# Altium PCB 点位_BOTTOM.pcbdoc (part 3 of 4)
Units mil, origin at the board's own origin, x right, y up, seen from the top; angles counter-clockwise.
Board outline 5102.8 x 4152 mil, 8 copper layers (Top Layer, GND1, 内层2, VCC, 内层4, Inner5, GND2, Bottom Layer); 209 components, 325 nets, 527 pads, 1119 vias.
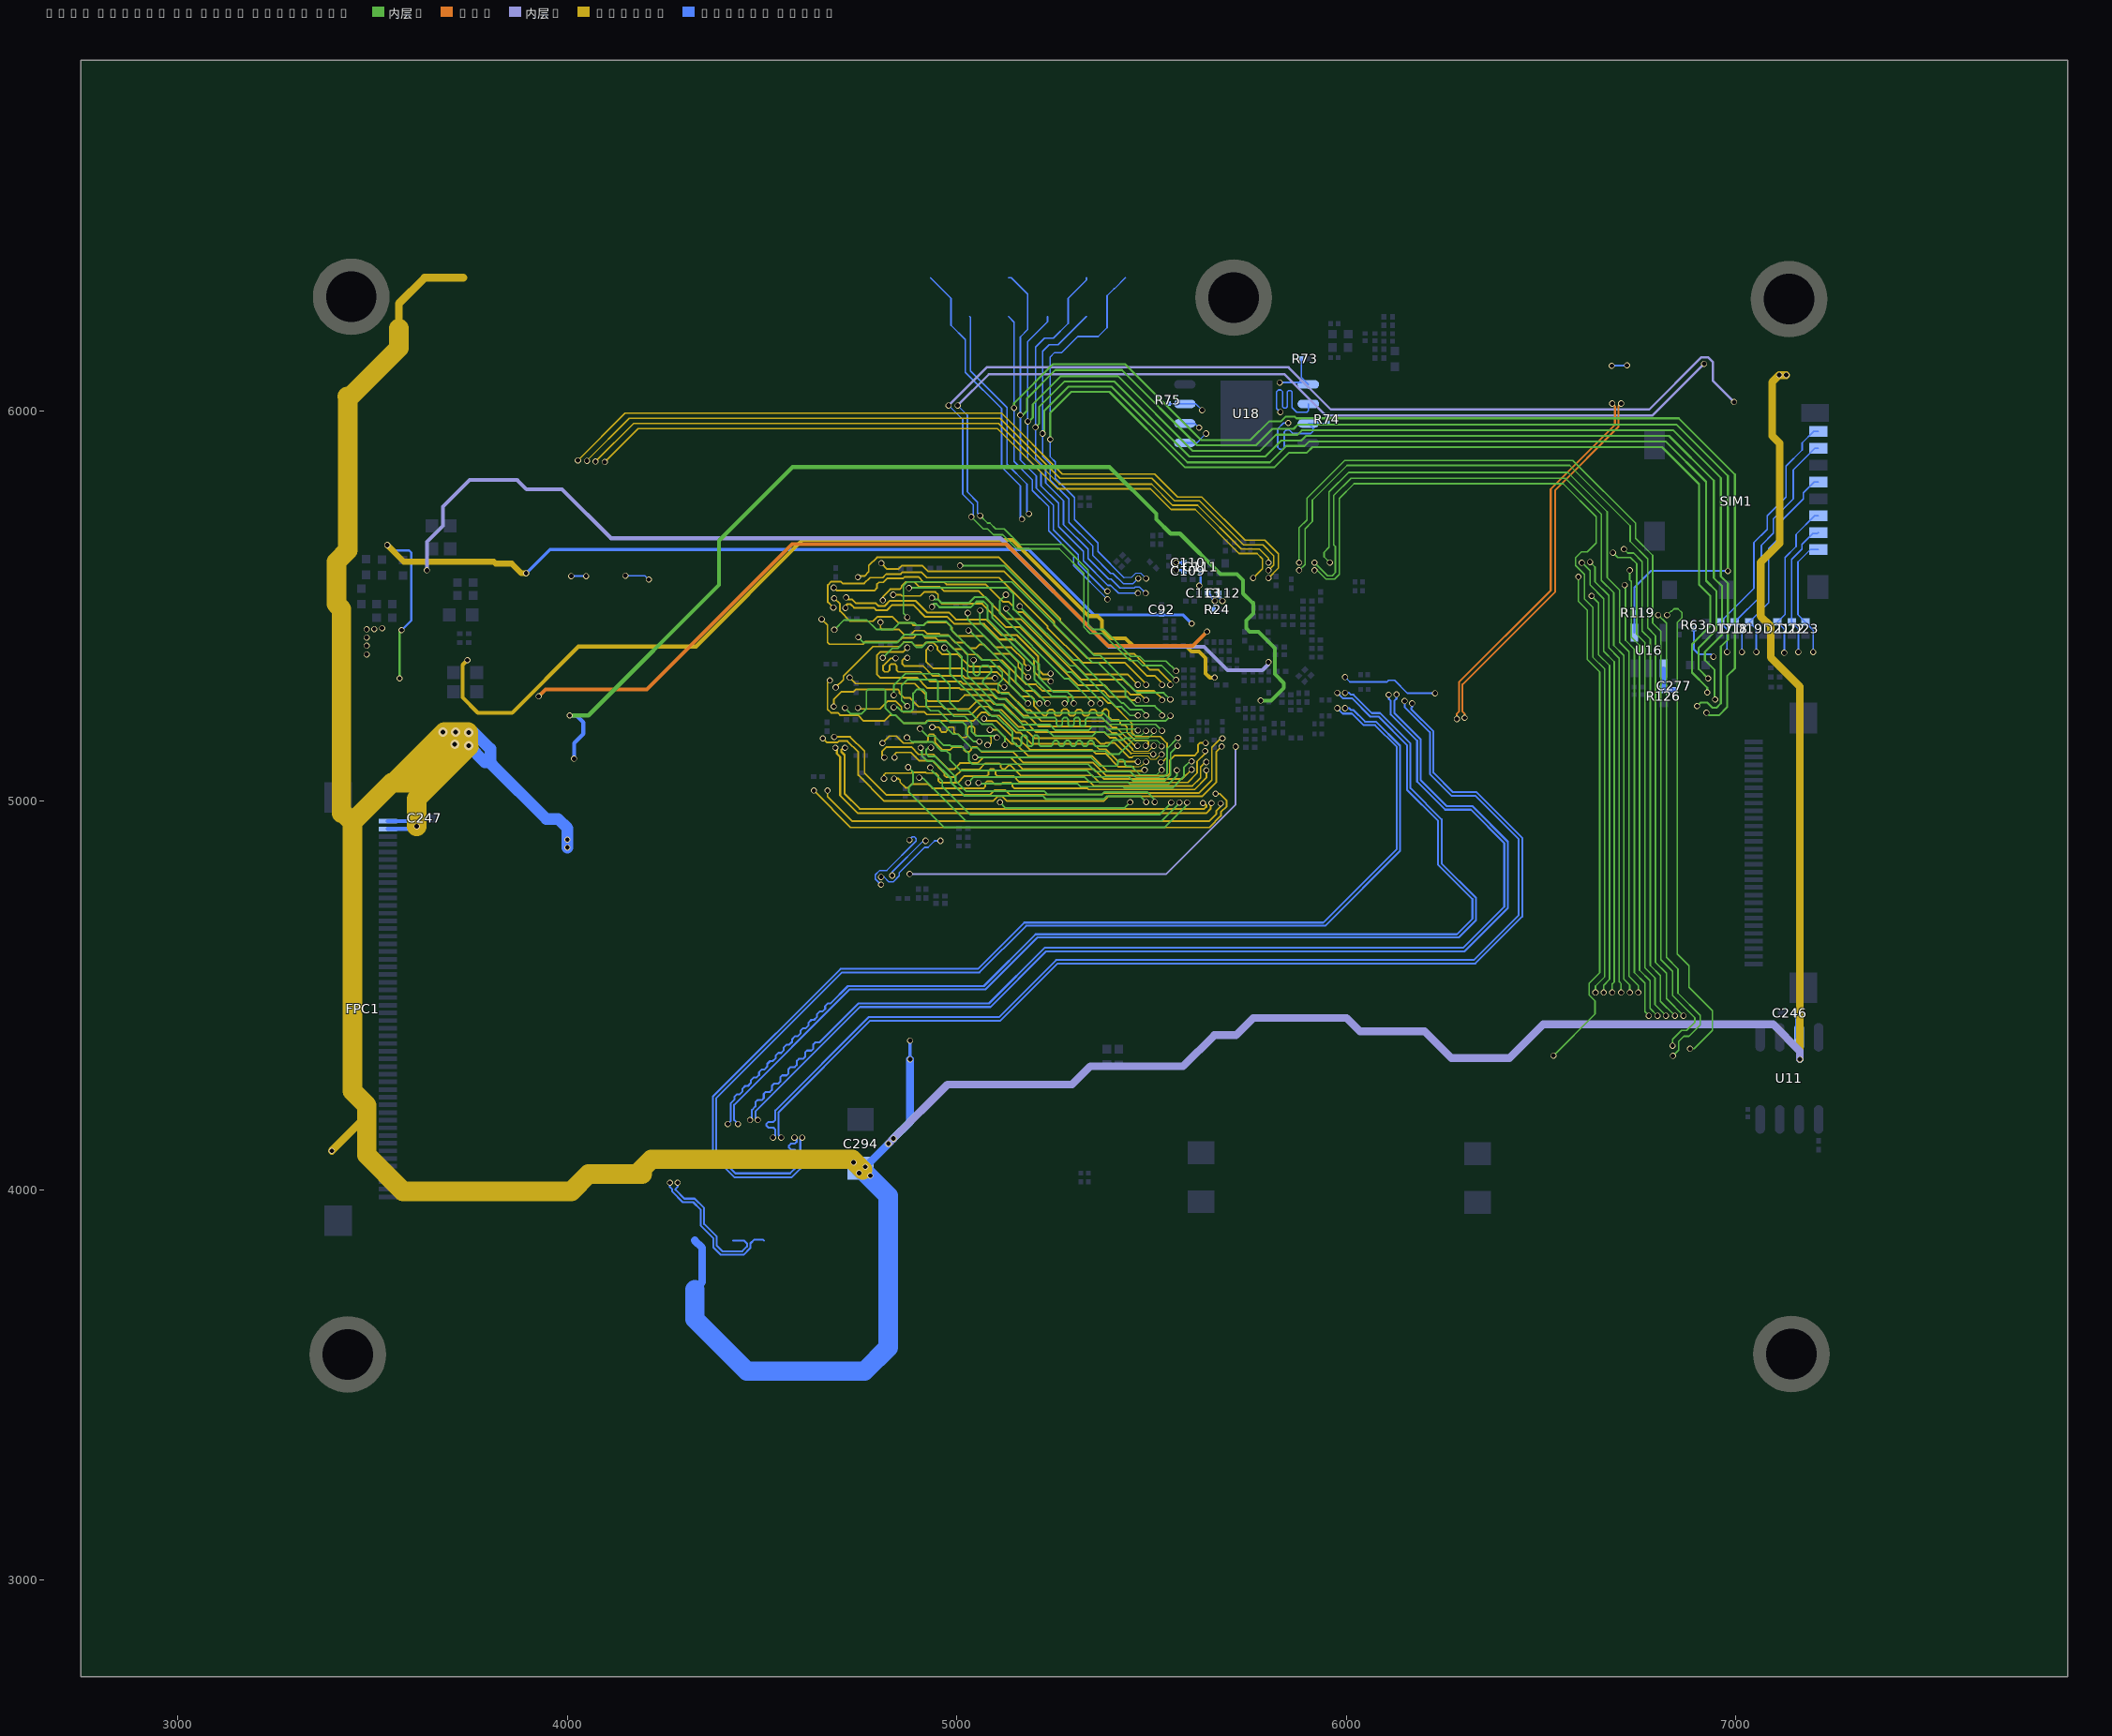
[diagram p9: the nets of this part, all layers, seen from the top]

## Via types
v1: diameter 15.75, hole 11.8, Top Layer to Bottom Layer, 496 vias
v2: diameter 15.7, hole 11.8, Top Layer to Bottom Layer, 335 vias
v3: diameter 15.75, hole 11.81, Top Layer to Bottom Layer, 279 vias
v4: diameter 24, hole 12, Top Layer to Bottom Layer, 9 vias

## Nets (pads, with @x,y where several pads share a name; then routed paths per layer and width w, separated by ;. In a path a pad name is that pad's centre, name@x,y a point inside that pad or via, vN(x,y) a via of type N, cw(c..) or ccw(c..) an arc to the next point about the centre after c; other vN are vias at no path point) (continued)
RGMII1-CLKIN:  | length 1314.1
  内层2 w4: v1(6531.8,4345.41) 6638.8,4452.41 6638.8,4486 6623.8,4501 6623.8,4531 6650.8,4558 6650.8,5331 6618.8,5363 6618.8,5489 6595.8,5512 v1(6595.8,5575)
RGMII1-MDC:  | length 1240.5
  内层2 w4: v1(6823.8,5477) 6833.8,5487 6835.8,5487 6841.8,5493 6851.8,5493 6861.8,5483 6861.8,5470 6849.8,5458 6849.8,4606 6879.8,4576 6879.8,4521 6939.8,4461 6939.8,4410 6892.8,4363 v1(6882.8,4363)
RGMII1-MDIO:  | length 1213.3
  内层2 w4: v1(6800.8,5477) 6821.8,5456 6821.8,4598 6851.8,4568 6851.8,4506 6908.8,4449 6908.8,4424 6879.8,4395 6866.8,4395 6853.8,4382 6853.8,4360 v1(6838.8,4345)
RGMII1-RXCK:  | length 2277
  内层2 w4: v1(5918.26,5591.69) 5925.11,5591.69 5947.8,5569 5969.8,5569 5981.8,5581 5981.8,5776 6019.8,5814 6556.8,5814 6641.8,5729 6641.8,5662 6618.8,5639 6603.8,5639 6588.8,5624 6588.8,5604 6611.8,5581 6611.8,5518 6632.8,5497 6632.8,5369 6663.68,5338.13 6663.68,4547.87 6639.8,4524 v1(6639.8,4507.49)
RGMII1-RXCTL:  | length 1043.8
  内层2 w4: v1(6629.8,5526) 6647.8,5508 6647.8,5375 6675.8,5347 6675.8,4541 6660.8,4526 v1(6660.8,4507.49)
RGMII1-RXD0:  | length 1140.5
  内层2 w4: v1(6604.8,5611) 6605.8,5611 6625.8,5591 6625.8,5554 6660.8,5519 6660.8,5384 6687.8,5357 6687.8,4534 6682.8,4529 v1(6682.8,4507.49)
RGMII1-RXD1:  | length 1138.6
  内层2 w4: v1(6625.8,5613) 6638.8,5600 6638.8,5562 6673.8,5527 6673.8,5393 6700.8,5366 6700.8,4535 6705.8,4530 v1(6705.8,4507.49)
RGMII1-RXD2:  | length 2272.4
  内层2 w4: v1(5918.26,5611.38) 5951.64,5578 5963.8,5578 5971.8,5586 5971.8,5653 5967.8,5657 5967.8,5784 6011.8,5828 6562.8,5828 6654.8,5736 6654.8,5566 6686.8,5534 6686.8,5399 6712.8,5373 6712.8,4542 6727.8,4527 v1(6727.8,4507.49)
RGMII1-RXD3:  | length 2237
  内层2 w4: v1(5957.63,5611.69) 5942.8,5626.52 5942.8,5638 5955.8,5651 5955.8,5793 6005.8,5843 6568.8,5843 6669.8,5742 6669.8,5573 6701.8,5541 6701.8,5407 6725.8,5383 6725.8,4549 6749.8,4525 v1(6749.8,4507.49)
RGMII1-TXCK:  | length 1131.7
  内层2 w4: v1(6714.8,5554) 6716.8,5552 6716.8,5412 6739.8,5389 6739.8,4559 6766.8,4532 6766.8,4458 v1(6776.8,4448)
RGMII1-TXCTL:  | length 1173.4
  内层2 w4: v1(6727.8,5592) 6727.8,5567 6731.8,5563 6731.8,5420 6752.8,5399 6752.8,4565 6779.8,4538 6779.8,4467 v1(6798.8,4448)
RGMII1-TXD0:  | length 1264.7
  内层2 w4: v1(6684.8,5637) 6696.8,5625 6729.8,5625 6745.8,5609 6745.8,5427 6766.8,5406 6766.8,4571 6792.8,4545 6792.8,4476 v1(6820.8,4448)
RGMII1-TXD1:  | length 1261
  内层2 w4: v1(6712.8,5646) 6722.8,5636 6737.8,5636 6759.8,5614 6759.8,5436 6780.8,5415 6780.8,4577 6806.8,4551 6806.8,4485 v1(6843.8,4448)
RGMII1-TXD2:  | length 2426.2
  内层2 w4: v1(5878.89,5591.69) 5893.8,5606.6 5893.8,5698 5912.8,5717 5912.8,5772 6001.8,5861 6573.8,5861 6728.8,5706 6728.8,5666 6773.8,5621 6773.8,5444 6793.8,5424 6793.8,4585 6821.8,4557 6821.8,4492 v1(6865.8,4448)
RGMII1-TXD3:  | length 2560.9
  内层2 w4: v1(5878.89,5611.38) 5878.89,5701.09 5898.8,5721 5898.8,5777 5995.8,5874 6581.8,5874 6742.8,5713 6742.8,5674 6786.8,5630 6786.8,5456 6807.8,5435 6807.8,4592 6837.8,4562 6837.8,4500 6894.8,4443 6894.8,4431 6873.8,4410 6860.8,4410 6837.8,4387 v1(6837.8,4371)
SAA0:  | length 442.3
  Inner5 w4.5: v3(5084.72,5181.97) 5104.66,5181.97 5140.66,5145.97 5151.72,5145.97 5182.72,5114.97 5346.72,5114.97 5385.72,5075.97 5478.91,5075.97 v3(5481.91,5078.97)
SAA1:  | length 473.4
  Inner5 w3: 5454.8,5086.98 5467.8,5087 5471.8,5088 v3(5485.72,5099.97)
  Inner5 w4.5: v3(5069.72,5210.97) 5070.17,5210.97 5076.13,5205.01 5102.22,5204.92 5146.67,5160.47 5157.73,5160.47 5187.23,5130.97 5346.22,5130.97 5356.19,5121 5380.96,5121 5414.98,5086.98 5454.8,5086.98 ; v3@5484.17,5099.97 v3(5485.72,5099.97)
SAA2:  | length 884.1
  Inner5 w3: 5449.59,5110.84 5452.75,5114 5490.69,5114 5498.72,5105.97 5510.72,5105.97 5523.72,5118.97 v3(5525.72,5118.97)
  Inner5 w4.5: v3(4745.72,5238.71) 4748.46,5235.97 4802.72,5235.97 4822.72,5255.97 4842.72,5255.97 4857.72,5240.97 4857.72,5232.47 4862.22,5227.97 4916.72,5227.97 4923.22,5221.47 5036.73,5221.47 5057.23,5241.97 5080.19,5241.97 5088.65,5233.51 5114.7,5233.46 5158.69,5189.47 5169.75,5189.47 5198.25,5160.97 5353.72,5160.97 5368.91,5145.78 5379.53,5145.78 5382.72,5148.97 5404.72,5148.97 5442.85,5110.84 5449.59,5110.84
SAA3:  | length 995.1
  内层2 w3: 5442.72,5145.97 5450.59,5153.85 5514.85,5153.85 5525.72,5142.97 v3(5525.72,5139.97)
  内层2 w4.5: v3(4712.71,5238.44) 4728.18,5222.97 4754.72,5222.97 4767.72,5235.97 4767.72,5280.97 4772.72,5285.97 4812.72,5285.97 4816.72,5281.97 4816.72,5236.97 4833.72,5219.97 4842.72,5219.97 4863.72,5198.97 4918.72,5198.97 4926.72,5206.97 4954.72,5206.97 4990.72,5170.97 5002.72,5170.97 5037.72,5135.97 5052.72,5135.97 5061.22,5127.47 5381.22,5127.47 5388.69,5120 5416.75,5120 5442.72,5145.97
SAA4:  | length 938.2
  Inner5 w3: 5447.23,5120.97 5502.72,5120.97 v3(5504.23,5119.46)
  Inner5 w4.5: v3(4683.72,5241.97) 4683.72,5259.97 4703.72,5279.97 4734.72,5279.97 4740.72,5285.97 4847.72,5285.97 4852.72,5280.97 4852.72,5275.97 4864.72,5263.97 4879.72,5263.97 4901.72,5241.97 4962.72,5241.97 4968.72,5235.97 5030.72,5235.97 5051.22,5256.47 5086.2,5256.47 5094.68,5247.99 5120.71,5247.96 5164.7,5203.97 5175.77,5203.97 5203.76,5175.97 5378.72,5175.97 5392.72,5161.97 5406.23,5161.97 5447.23,5120.97
SAA5:  | length 1091.8
  Inner5 w4.5: v3(4688.72,5290.97) 4708.72,5310.97 4708.72,5319.97 4784.72,5395.97 4852.72,5395.97 4863.72,5406.97 4883.72,5406.97 4891.72,5398.97 4912.72,5398.97 4919.72,5405.97 4939.83,5405.97 4949.72,5396.08 4949.72,5389.08 4962.83,5375.97 5001.72,5375.97 5033.22,5344.47 5108.88,5344.47 5170.87,5282.48 5195.87,5282.48 5212.38,5265.97 5372.72,5265.97 5387.72,5250.97 5396.72,5250.97 5449.72,5197.97 5449.72,5174.97 5459.72,5164.97 5521.83,5164.97 5539.72,5147.08 5539.72,5111.97 5526.72,5098.97 v3(5523.72,5098.97)
SAB0:  | length 870.8
  内层2 w3: 5447.72,5160.97 5491.72,5160.97 5505.77,5175.02 v3(5505.77,5179.6)
  内层2 w4.5: v3(4967.72,5392.97) 4982.72,5377.97 4982.72,5324.95 5090.7,5216.97 5102.21,5216.97 5142.72,5176.46 5142.72,5152.47 5155.22,5139.97 5161.09,5139.97 5165.59,5144.47 5165.59,5163.47 5170.09,5167.97 5176.09,5167.97 5180.59,5163.47 5180.59,5144.47 5185.09,5139.97 5191.09,5139.97 5195.59,5144.47 5195.59,5163.47 5200.09,5167.97 5206.09,5167.97 5210.59,5163.47 5210.59,5144.47 5215.09,5139.97 5242,5139.97 5246.5,5144.47 5246.5,5149.85 5251,5154.35 5257,5154.35 5261.5,5149.85 5261.5,5144.47 5266,5139.97 5272,5139.97 5276.5,5144.47 5276.5,5149.85 5281,5154.35 5287,5154.35 5291.5,5149.85 5291.5,5144.47 5296,5139.97 5302,5139.97 5306.5,5144.47 5306.5,5149.85 5311,5154.35 5317,5154.35 5321.5,5149.85 5321.5,5144.47 5326,5139.97 5332,5139.97 5336.5,5144.47 5336.5,5149.85 5341,5154.35 5347,5154.35 5351.5,5149.85 5351.5,5144.47 5356,5139.97 5385.72,5139.97 5401.72,5155.97 5426.72,5155.97 5431.72,5160.97 5447.72,5160.97
SAB1:  | length 764.3
  内层2 w4.5: v3(5042.72,5361.22) 5042.72,5326.48 5047.83,5321.37 5054.19,5321.37 5058.72,5325.9 5058.72,5340.67 5065.03,5346.97 5079.72,5346.97 5088.72,5337.97 5088.72,5330.97 5066.92,5309.17 5066.92,5302.28 5108.73,5260.47 5124.22,5260.47 5170.72,5213.97 5251.16,5213.97 5255.66,5209.47 5255.66,5196.02 5260.16,5191.52 5266.16,5191.52 5270.66,5196.02 5270.66,5209.47 5275.16,5213.97 5281.16,5213.97 5285.66,5209.47 5285.66,5196.02 5290.16,5191.52 5296.16,5191.52 5300.66,5196.02 5300.66,5209.47 5305.16,5213.97 5311.16,5213.97 5315.66,5209.47 5315.66,5196.02 5320.16,5191.52 5326.16,5191.52 5330.66,5196.02 5330.66,5209.47 5335.16,5213.97 5371.72,5213.97 5389.69,5196 5510.37,5196 v3(5526.77,5179.6)
SAB2:  | length 875.8
  内层2 w4.5: v3(4746.6,5419.95) 4760.58,5405.97 4845.72,5405.97 4866.72,5426.97 4910.72,5426.97 4914.72,5422.97 4981.21,5422.97 5027.72,5376.46 5027.72,5320.97 5102.72,5245.97 5118.21,5245.97 5168.21,5195.97 5237.72,5195.97 5252.72,5180.97 5337.72,5180.97 5348.22,5191.47 5379.22,5191.47 5386.72,5183.97 5461.83,5183.97 v3(5464.8,5181)
SAB3:  | length 852.6
  内层2 w3: 5425.72,5173.97 5445.72,5173.97 5451.69,5168 5474.16,5168 v3(5485.76,5179.6)
  内层2 w4.5: v3(4809.72,5366.97) 4833.72,5390.97 4848.72,5390.97 4865.72,5407.97 4882.72,5407.97 4896.72,5393.97 4909.72,5393.97 4923.72,5407.97 4973.7,5407.97 5012.72,5368.95 5012.72,5315.46 5096.71,5231.47 5108.22,5231.47 5158.72,5180.97 5232.72,5180.97 5247.72,5165.97 5347.72,5165.97 5358.72,5176.97 5378.72,5176.97 5385.72,5169.97 5421.72,5169.97 5425.72,5173.97
SAB4:  | length 883.9
  Inner5 w3: 5450.72,5130.97 5453.72,5127.97 5492.72,5127.97 v3(5505.72,5140.97)
  Inner5 w4.5: v3(4724.72,5315.97) 4739.72,5300.97 4891.72,5300.97 4919.72,5272.97 4919.72,5261.97 4925.97,5255.72 5004.47,5255.72 5019.72,5270.97 5092.21,5270.97 5100.71,5262.47 5126.72,5262.46 5170.71,5218.47 5181.78,5218.47 5209.28,5190.97 5380.72,5190.97 5397.72,5173.97 5408.72,5173.97 5450.72,5131.97 5450.72,5130.97
SAB5:  | length 965.2
  Inner5 w4.5: v3(4673.72,5308.97) 4667.72,5302.97 4667.72,5234.97 4676.72,5225.97 4693.72,5225.97 4699.72,5219.97 4745.72,5219.97 4760.72,5204.97 4813.72,5204.97 4828.72,5219.97 4842.72,5219.97 4863.97,5198.72 4916.47,5198.72 4922.72,5204.97 5041.72,5204.97 5063.72,5226.97 5074.68,5226.97 5082.62,5219.03 5108.69,5218.96 5152.68,5174.97 5163.74,5174.97 5192.74,5145.97 5351.73,5145.97 5365.23,5132.47 5382.7,5132.47 5414.94,5100.23 v3(5464.86,5100.23)
SCKE0-A:  | length 436.4
  内层2 w4.5: v3(4837.72,5270.97) 4837.72,5295.97 4867.72,5325.97 4952.72,5325.97 4981.72,5296.97 4981.72,5252.97 5003.72,5230.97 5029.56,5230.97 5063.81,5196.72 5090.44,5196.72 5123.11,5164.05 v3(5123.11,5143.36)
SCKE0-B:  | length 278.1
  Inner5 w4.5: v3(4872.72,5366.97) 4866.22,5366.97 4859.72,5360.47 4859.72,5350.97 4864.72,5345.97 4912.72,5345.97 4937.72,5320.97 5015.7,5320.97 5021.71,5314.96 v3(5097.71,5314.96)
SCKE1-A:  | length 360.8
  内层2 w4.5: v3(4837.72,5239.97) 4847.72,5239.97 4858.72,5228.97 4880.72,5228.97 4887.72,5235.97 4887.72,5275.97 4897.72,5285.97 4912.72,5285.97 4920.72,5277.97 4920.72,5242.97 4932.72,5230.97 4952.72,5230.97 4981.72,5201.97 5014.72,5201.97 5023.72,5192.97 5023.71,5170.98 5042.21,5152.47 5057.72,5152.47 v3(5057.72,5151.97)
SCKE1-B:  | length 409.8
  Inner5 w4.5: v3(4842.72,5365.97) 4829.72,5365.97 4810.72,5346.97 4810.72,5334.97 4814.72,5330.97 4822.54,5330.97 4827.04,5335.47 4827.04,5346.47 4831.54,5350.97 4840.54,5350.97 4845.04,5346.47 4845.04,5335.47 4849.54,5330.97 4905.72,5330.97 4930.72,5305.97 5010.19,5305.97 5016.19,5299.97 5106.72,5299.97 5115.23,5291.46 v3(5121.21,5291.46)
SCS0-A:  | length 413.4
  内层2 w4.5: v3(4872.72,5242.97) 4857.72,5257.97 4857.72,5295.97 4872.72,5310.97 4946.22,5310.97 4950.72,5306.47 4950.72,5257.97 4992.22,5216.47 5020.73,5216.47 5038.22,5198.98 5038.22,5176.98 5048.23,5166.97 5097.72,5166.97 v3(5102.72,5161.97)
SCS0-B:  | length 880.7
  Inner5 w4.5: v3(4872.72,5392.97) 4861.72,5381.97 4802.72,5381.97 4794.72,5373.97 4794.72,5323.97 4802.72,5315.97 4897.72,5315.97 4924.33,5289.36 5006.29,5289.36 5010.18,5285.47 5098.22,5285.47 5106.72,5276.97 5132.72,5276.97 5176.72,5232.97 5187.79,5232.97 5216.29,5204.47 5383.22,5204.47 5399.72,5187.97 5409.72,5187.97 5456.72,5140.97 v3(5463.72,5140.97)
SCS1-A:  | length 253.4
  Inner5 w4.5: v3(4936.72,5188.97) 4952.76,5188.97 4957.26,5184.47 4957.26,5180.47 4961.76,5175.97 4970.76,5175.97 4975.26,5180.47 4975.26,5184.47 4979.76,5188.97 4989.72,5188.97 4992.72,5185.97 4992.72,5175.47 4997.22,5170.97 5003.72,5170.97 5012.28,5162.41 5023.22,5162.41 5027.72,5166.91 5027.72,5186.47 5032.22,5190.97 5041.22,5190.97 5045.72,5186.47 5045.72,5171.47 5050.22,5166.97 5083.22,5166.97 5087.72,5162.47 5087.72,5147.47 5083.22,5142.97 v3(5078.72,5142.97)
SCS1-B:  | length 851
  Inner5 w4.5: v3(4932.72,5391.97) 4926.72,5391.97 4920.72,5385.97 4920.72,5357.97 4938.72,5339.97 5017.21,5339.97 5027.21,5329.97 5102.87,5329.97 5164.86,5267.98 5191.27,5267.98 5197.47,5261.78 5197.47,5244.06 5223.56,5217.97 5228.06,5217.97 5232.56,5222.47 5232.56,5229.47 5237.06,5233.97 5246.06,5233.97 5250.56,5229.47 5250.56,5222.47 5255.06,5217.97 5264.06,5217.97 5268.56,5222.47 5268.56,5230.77 5273.07,5235.28 5282.05,5235.28 5286.56,5230.77 5286.56,5222.47 5291.06,5217.97 5300.06,5217.97 5304.56,5222.47 5304.56,5229.47 5309.06,5233.97 5318.06,5233.97 5322.56,5229.47 5322.56,5222.47 5327.06,5217.97 5336.06,5217.97 5340.56,5222.47 5340.56,5229.47 5345.06,5233.97 5354.06,5233.97 5358.56,5229.47 5358.56,5222.47 5363.06,5217.97 5369.22,5217.97 5373.72,5222.47 5373.72,5230.27 5378.54,5235.09 5384.91,5235.09 5389.72,5230.28 5389.72,5215.97 5397.72,5207.97 5414.72,5207.97 5419.72,5202.97 5419.72,5197.97 5423.97,5193.72 5432.47,5193.72 5436.72,5189.47 5436.72,5175.97 5457.72,5154.97 5487.72,5154.97 5491.8,5150.89 5491.8,5144.68 5488.1,5140.97 v3(5484.72,5140.97)
SDC0-CLK: D19.2 SIM1.5 | length 523.6
  Bottom Layer w4: v1(7052.8,5382) 7052.8,5440.4 D19.2@7034.8,5458.4 7084.8,5508.4 7084.8,5648 7115.8,5679 7115.8,5717 7173.8,5775 7173.8,5791 7201.51,5818.7 SIM1.5@7211.94,5818.7
SDC0-CMD: D21.2 SIM1.3 | length 408.4
  Bottom Layer w4: v1(7124.8,5380) 7124.8,5440.4 D21.2@7106.8,5458.4 7126.8,5478.4 7126.8,5625 7154.8,5653 7154.8,5684 7202.89,5732.09 SIM1.3@7211.94,5732.09
SDC0-D0: D18.1 SIM1.7 | length 625.3
  Bottom Layer w4: v1(7015.8,5382) 7015.8,5439.8 D18.1@6997.04,5458.56 7065.8,5527.32 7065.8,5656 7096.8,5687 7096.8,5724 7147.8,5775 7147.8,5850 7203.12,5905.31 SIM1.7@7211.94,5905.31
SDC0-D1: D17.2 SIM1.8 | length 685.3
  Bottom Layer w4: v1(6977.8,5382) 6977.8,5440.4 D17.2@6959.8,5458.4 7046.8,5545.4 7046.8,5663 7080.8,5697 7080.8,5732 7128.8,5780 7128.8,5859 7170.8,5901 7170.8,5919 7200.43,5948.62 SIM1.8@7211.94,5948.62
SDC0-D2: D23.2 SIM1.1 | length 312.7
  Bottom Layer w4: v1(7198.8,5382) 7198.8,5438.4 D23.2@7178.8,5458.4 7159.8,5477.4 7159.8,5613 7192.28,5645.48 SIM1.1@7211.94,5645.48
SDC0-D3: D22.1 SIM1.2 | length 348.7
  Bottom Layer w4: v1(7160.8,5382) 7160.8,5441.4 D22.1@7143.8,5458.4 7143.8,5620 7169.8,5646 7169.8,5658 7197.8,5686 7209.15,5686 SIM1.2@7211.94,5688.78
SDC0-DET: R63.1 | length 362.5
  Bottom Layer w4: v1(5996.69,5317.4) 6009.1,5305 6104.8,5305 6108.8,5309 6123.8,5309 6156.8,5276 v1(6227.8,5276)
  Bottom Layer w5: R63.1@6892.8,5441.49 6892.8,5388 6904.8,5376 6936.8,5376 v2(6942.8,5370)
SDC1-CMD:  | length 64.1
  Bottom Layer w4: v1(4148.8,5578) 4198.8,5578 v1(4208.8,5568)
SDC2-CLK:  | length 200.6
  Bottom Layer w4: v1(4805.22,4784.53) 4790.8,4798.94 4790.8,4810 4801.8,4821 4819.8,4821 4895.47,4896.67 4895.47,4902.33 4890.8,4907 4885.8,4907 v1(4877.8,4899)
SDC2-CMD:  | length 206.4
  Bottom Layer w4: v1(4805.22,4804.21) 4812.59,4804.21 4824.8,4792 4836.72,4792 4851.8,4807.09 4851.8,4815 4916.8,4880 4925.8,4880 4941.72,4895.91 4941.72,4897 v1(4957.8,4897)
SDC2-DS:  | length 1059.7
  内层4 w5: v1(4878.8,4812) 5537.8,4812 5715.8,4990 v1(5715.8,5138.93)
SDC2-RST:  | length 128.1
  Bottom Layer w4: v1(4833.8,4808) 4833.8,4817 4913.8,4897 v1(4919.8,4897)
SDQ0:  | length 820.3
  内层2 w4.5: v3(4871.72,5161.97) 4873.72,5161.97 4884.72,5150.97 4937.72,5150.97 4960.69,5128 4973.69,5128 4982.72,5118.97 4982.72,5103.97 5009.22,5077.47 5334.56,5077.47 5350.56,5061.47 5441.22,5061.47 5451.16,5051.53 5534.28,5051.53 5548.72,5065.97 5548.72,5123.18 v3(5566.77,5141.23)
SDQ1:  | length 804.6
  内层2 w3: 5457.72,5061.97 5460.72,5058.97 5518.72,5058.97 5521.72,5061.97
  内层2 w4.5: v3(4905.2,5184.92) 4924.15,5165.97 4942.72,5165.97 4966.22,5142.47 4982.56,5142.47 4984.58,5140.45 5010.35,5140.45 5030.97,5119.83 5030.97,5102.72 5039.72,5093.97 5336.72,5093.97 5356.22,5074.47 5445.22,5074.47 5457.72,5061.97 ; 5521.72,5061.97 5531.72,5061.97 5539.72,5069.97 5539.72,5133.97 5566.98,5161.23 v3(5567.76,5161.23)
SDQ2:  | length 527
  内层2 w3: 5468.72,5067.97 5470.72,5065.97 5512.78,5065.97 v3(5525.8,5079)
  内层2 w4.5: v3(5046.72,5111.97) 5047.72,5110.97 5344.72,5110.97 5366.72,5088.97 5408.52,5088.97 5413.02,5093.47 5413.02,5101.47 5417.52,5105.97 5426.52,5105.97 5431.02,5101.47 5431.02,5093.47 5435.52,5088.97 5447.72,5088.97 5468.72,5067.97
SDQ3:  | length 346.2
  内层2 w4.5: v3(5110.72,4995.97) 5125.47,4981.22 5429.97,4981.22 v3(5444.72,4995.97)
SDQ4:  | length 594.1
  内层2 w4.5: v3(5055.72,5046.22) 5057.97,5043.97 5309.72,5043.97 5317.72,5035.97 5427.72,5035.97 5430.72,5032.97 5553.72,5032.97 5582.72,5061.97 5582.72,5084.97 5598.72,5100.97 v3(5602.72,5100.97)
SDQ5:  | length 734.6
  内层2 w4.5: v3(4903.43,5059.35) 4905.11,5057.67 4913.02,5057.67 5022.47,4948.22 5525.95,4948.22 5571.24,4993.51 v3(5571.24,4995.51)
SDQ6:  | length 573.3
  内层2 w4.5: v3(5028.72,5046.22) 5043.47,5060.97 5327.72,5060.97 5340.72,5047.97 5438.72,5047.97 5444.72,5041.97 5542.72,5041.97 5564.65,5063.9 v3(5564.65,5078.25)
SDQ7:  | length 855.7
  内层2 w4.5: v3(4874.72,5085.97) 4887.72,5072.97 4887.72,5045.97 4876.72,5034.97 4876.72,5021.97 4966.97,4931.72 5533.47,4931.72 5591.34,4989.59 v3(5591.34,4995.41)
SDQ8:  | length 999.4
  Inner5 w4.5: v3(4808.72,5147.97) 4826.72,5165.97 4844.72,5165.97 4862.72,5147.97 4887.72,5147.97 4890.72,5150.97 4921.22,5150.97 4925.72,5155.47 4925.72,5166.47 4930.22,5170.97 4939.22,5170.97 4943.72,5166.47 4943.72,5149.97 4962.72,5130.97 4982.72,5130.97 4989.72,5137.97 5013.95,5137.97 5018.45,5133.47 5018.45,5130.47 5022.95,5125.97 5031.95,5125.97 5036.45,5130.47 5036.45,5133.47 5040.95,5137.97 5050.72,5137.97 5062.72,5125.97 5142.82,5125.97 5170.82,5097.97 5349.73,5097.97 5382.98,5064.72 5541.47,5064.72 5546.72,5069.97 5546.72,5103.97 5558.72,5115.97 5609.72,5115.97 5618.72,5124.97 5618.72,5143.72 5623.23,5148.23 v3(5638.77,5148.23)
SDQ9:  | length 937.6
  Inner5 w4.5: v3(4839.72,5110.97) 4839.72,5119.47 4844.22,5123.97 4881.72,5123.97 4902.72,5102.97 4935.72,5102.97 4967.72,5070.97 4967.72,5065.47 4972.22,5060.97 4993.88,5060.97 5012.8,5079.89 5056.64,5079.89 5072.72,5095.97 5108.22,5095.97 5112.72,5091.47 5112.72,5085.97 5117.72,5080.97 5122.72,5080.97 5132.03,5090.28 5138.41,5090.28 5163.72,5064.97 5347.72,5064.97 5365.72,5046.97 5592.72,5046.97 5616.72,5070.97 5616.72,5100.97 5637.44,5121.69 v3(5637.44,5127.61)
SDQ10:  | length 943.4
  Inner5 w4.5: v3(4812.72,5056.97) 4812.72,5066.47 4817.22,5070.97 4882.72,5070.97 4884.72,5072.97 4919.72,5072.97 4921.72,5070.97 4945.72,5070.97 4952.72,5063.97 4952.72,5050.47 4957.22,5045.97 5002.22,5045.97 5019.64,5063.39 5076.82,5063.39 5081.32,5067.89 5081.32,5076.47 5085.82,5080.97 5094.82,5080.97 5099.32,5076.47 5099.32,5067.89 5103.82,5063.39 5145.3,5063.39 5160.22,5048.47 5341.21,5048.47 5351.71,5037.97 5604.72,5037.97 5625.72,5058.97 5625.72,5086.97 5638,5099.25 v3(5640.64,5099.25)
SDQ11:  | length 883.8
  Inner5 w4.5: v3(4838.72,5056.97) 4849.72,5056.97 4854.22,5052.47 4854.22,5047.47 4868.53,5033.16 4874.91,5033.16 4884.72,5042.97 4925.72,5042.97 4936.72,5031.97 5068.72,5031.97 5072.72,5035.97 5072.72,5045.39 5077.22,5049.89 5089.8,5049.89 5096.72,5042.97 5113.72,5042.97 5117.72,5046.97 5138.22,5046.97 5142.72,5042.47 5142.72,5035.97 5146.72,5031.97 5335.09,5031.97 5338.09,5028.97 5610.72,5028.97 5640.65,5058.9 v3(5640.65,5078.25)
SDQ12:  | length 1177.4
  Inner5 w4.5: v3(4632.72,5025.97) 4727.22,4931.47 5648.22,4931.47 5677.72,4960.97 5677.72,4970.97 5692.72,4985.97 5692.72,4999.97 5674.72,5017.97 v3(5664.38,5017.97)
SDQ13:  | length 1078.9
  Inner5 w4.5: v3(4667.72,5025.97) 4667.72,5010.97 4730.72,4947.97 5648.72,4947.97 5665.72,4964.97 5665.72,4973.98 5677.19,4985.45 v3(5677.19,4992.97)
SDQ14:  | length 1242
  Inner5 w4.5: v3@4655.72,5160.06 4665.81,5149.97 4693.72,5149.97 4696.91,5153.16 4718.53,5153.16 4746.72,5124.97 4746.72,5065.97 4813.72,4998.97 5092.72,4998.97 5104.72,5010.97 5116.72,5010.97 5128.72,4998.97 5376.72,4998.97 5388.72,5010.97 5629.72,5010.97 5665.72,5046.97 5665.72,5124.95 v3(5680.02,5139.25)
  other v3: 4655.58,5160.09
SDQ15:  | length 1210.6
  Inner5 w4.5: v3(4684.72,5163.97) 4725.72,5163.97 4762.72,5126.97 4762.72,5070.97 4818.59,5015.1 5085.51,5015.1 5097.88,5027.47 5123.56,5027.47 5135.56,5015.47 5372.22,5015.47 5376.72,5019.97 5621.72,5019.97 5654.72,5052.97 5654.72,5136.97 5677.72,5159.97 v3(5681.72,5159.97)
SDQ16:  | length 252.1
  内层2 w4.5: v3(5029.72,5436.97) 5032.72,5436.97 5134.22,5335.47 5134.22,5299.13 5182.72,5250.63 v3(5182.72,5249.97)
SDQ17:  | length 311.1
  内层2 w4.5: v3(5027.72,5481.97) 5027.72,5465.31 5150.72,5342.31 5150.72,5305.97 5206.72,5249.97 v3(5211.72,5249.97)
SDQ18:  | length 907.7
  内层2 w4.5: v3(4872.8,5471) 4862.72,5481.08 4862.72,5551.97 4872.72,5561.97 5140.73,5561.97 5347.73,5354.97 5362.72,5354.97 5432.72,5284.97 5432.72,5269.97 5459.22,5243.47 5508.33,5243.47 5526.76,5225.04 v3(5526.76,5218.97)
SDQ19:  | length 442.5
  内层2 w4.5: v3(5161.72,5498.97) 5161.72,5498.62 5298.37,5361.97 5311.72,5361.97 5422.72,5250.97 5427.72,5250.97 5444.72,5233.97 5474.72,5233.97 5485.76,5222.93 v3(5485.76,5218.97)
SDQ20:  | length 747
  内层2 w4.5: v3(4876.72,5545.97) 4877.72,5546.97 5128.71,5546.97 5145.22,5530.46 5145.22,5491.78 5290.54,5346.46 5303.89,5346.46 5409.38,5240.97 5422.72,5240.97 5444.63,5219.06 v3(5464.85,5219.06)
SDQ21:  | length 350.3
  内层2 w4.5: v3(5126.72,5493.97) 5126.72,5486.94 5283.71,5329.95 5294.74,5329.95 5367.72,5256.97 v3(5367.72,5249.97)
SDQ22:  | length 389
  内层2 w4.5: v3(5125.72,5528.97) 5110.22,5513.47 5110.22,5480.1 5276.88,5313.44 5287.91,5313.44 5344.72,5256.63 v3(5344.72,5249.97)
SDQ23:  | length 682.8
  内层2 w4.5: v3(5007.8,5604) 5121.69,5604 5352.72,5372.97 5367.72,5372.97 5463.69,5277 5531.17,5277 v3(5548.13,5260.04)
SDQ24:  | length 976.9
  Inner5 w4.5: v3(4745.72,5573.97) 4748.72,5576.97 4762.72,5576.97 4773.72,5587.97 4773.72,5603.97 4794.72,5624.97 5108.06,5624.97 5265.72,5467.31 5265.72,5460.97 5349.72,5376.97 5455.72,5376.97 5467.72,5364.97 5467.72,5364.47 5496.22,5335.97 5517.72,5335.97 5547.76,5305.93 v3(5547.76,5297.71)
SDQ25:  | length 865.6
  Inner5 w4.5: v3(4805.72,5609.97) 4820.72,5594.97 4849.72,5594.97 4858.72,5603.97 4910.72,5603.97 4925.22,5589.47 5120.22,5589.47 5249.22,5460.47 5249.22,5451.47 5334.72,5365.97 5442.72,5365.97 5487.72,5320.97 5507.72,5320.97 5526.76,5301.93 v3(5526.76,5297.71)
SDQ26:  | length 1022.3
  Inner5 w4.5: v3(4682.72,5495.97) 4668.72,5509.97 4668.72,5553.97 4677.72,5562.97 4701.72,5562.97 4706.72,5557.97 4762.09,5557.97 4777.09,5572.97 4809.72,5572.97 4818.72,5581.97 4855.72,5581.97 4860.72,5586.97 4908.72,5586.97 4922.72,5572.97 5108.72,5572.97 5232.72,5448.97 5232.72,5444.63 5323.37,5353.97 5431.72,5353.97 5485.76,5299.93 v3(5485.76,5297.71)
SDQ27:  | length 922.1
  Inner5 w4.5: v3(4683.72,5546.97) 4690.72,5539.97 4788.72,5539.97 4794.63,5545.88 4794.63,5555.88 4799.72,5560.97 4810.72,5560.97 4820.72,5570.97 4861.72,5570.97 4865.72,5574.97 4900.72,5574.97 4914.72,5560.97 4967.72,5560.97 4973.22,5555.47 5073.22,5555.47 5117.72,5510.97 5132.72,5510.97 5144.72,5498.97 5144.72,5493.97 5154.72,5483.97 5170.04,5483.97 5330.04,5323.97 5438.68,5323.97 v3(5464.85,5297.8)
SDQ28:  | length 468.5
  Inner5 w4.5: v3(4803.72,5457.97) 4803.72,5444.47 4808.22,5439.97 4850.72,5439.97 4863.72,5426.97 4881.72,5426.97 4891.72,5436.97 4915.72,5436.97 4923.72,5428.97 4954.72,5428.97 4957.72,5425.97 4976.72,5425.97 4996.72,5405.97 5019.4,5405.97 5033.4,5391.97 5048.72,5391.97 5057.72,5400.97 5069.38,5400.97 5092.88,5377.47 5136.22,5377.47 5157.72,5355.97 5157.72,5342.63 5182.28,5318.07 v3(5182.82,5318.07)
SDQ29:  | length 944.9
  Inner5 w4.5: v3(4652.64,5465.97) 4667.72,5450.89 4667.72,5406.47 4672.22,5401.97 4758.72,5401.97 4765.72,5408.97 4849.72,5408.97 4858.72,5417.97 4887.78,5417.97 4896.8,5427 4910.69,5427 4919.72,5417.97 4945.72,5417.97 4952.72,5410.97 4971.72,5410.97 4993.22,5389.47 5012.56,5389.47 5026.56,5375.47 5051.22,5375.47 5065.72,5360.97 5115.72,5360.97 5177.71,5298.98 5202.71,5298.98 5219.22,5282.47 5376.22,5282.47 5392.22,5266.47 5438.22,5266.47 5446.26,5258.43 v3(5464.85,5258.43)
SDQ30:  | length 777
  Inner5 w4.5: v3(4836.72,5528.97) 4855.72,5528.97 4858.72,5525.97 4905.72,5525.97 4915.72,5535.97 4944.72,5535.97 4951.72,5528.97 4951.72,5515.97 4961.72,5505.97 5065.33,5505.97 5125.33,5445.97 5161.36,5445.97 5310.36,5296.97 5378.72,5296.97 5394.72,5280.97 5437.72,5280.97 5445.69,5273 5471.1,5273 v3(5485.76,5258.34)
SDQ31:  | length 871.7
  Inner5 w4.5: v3(4809.72,5514.97) 4809.72,5523.97 4828.72,5542.97 4853.22,5542.97 4857.72,5547.47 4857.72,5550.97 4868.72,5561.97 4890.71,5561.97 4903.71,5548.97 4956.72,5548.97 4966.72,5538.97 5055.67,5538.97 5128.67,5465.97 5164.7,5465.97 5319.7,5310.97 5427.72,5310.97 5456.69,5282 5506.69,5282 5526.76,5261.93 v3(5526.76,5258.34)
SDQM0:  | length 692.9
  内层2 w4.5: v3(4931.72,5084.97) 4931.72,5081.97 4962.72,5050.97 4962.72,5035.97 5033.97,4964.72 5521.45,4964.72 5550.24,4993.51 5550.24,4995.34 v3(5550.41,4995.51)
SDQM1:  | length 886.2
  Inner5 w4.5: v3(4813.72,5110.97) 4807.72,5116.97 4807.72,5125.97 4819.72,5137.97 4882.72,5137.97 4901.72,5118.97 4939.72,5118.97 4977.72,5080.97 4992.72,5080.97 5008.14,5096.39 5053.14,5096.39 5067.72,5110.97 5138.72,5110.97 5168.22,5081.47 5351.22,5081.47 5376.72,5055.97 5578.72,5055.97 v3(5602.72,5079.97)
SDQM2:  | length 313
  内层2 w4.5: v3(5059.72,5488.97) 5058.72,5487.97 5058.72,5458.02 5060.72,5456.02 5060.72,5455.65 5167.72,5348.65 5167.72,5312.31 5197.06,5282.97 5199.72,5282.97 v3(5232.72,5249.97)
SDQM3:  | length 608.1
  Inner5 w4.5: v3(4684.72,5519.97) 4699.72,5504.97 4699.72,5486.97 4725.72,5460.97 4784.72,5460.97 4795.72,5471.97 4834.83,5471.97 4849.83,5456.97 4881.72,5456.97 4887.72,5450.97 4915.72,5450.97 4922.72,5457.97 4973.72,5457.97 4987.72,5443.97 4987.72,5435.97 5000.97,5422.72 5070.97,5422.72 5099.72,5393.97 5139.72,5393.97 5172.72,5360.97 5172.72,5350.97 v3(5182.72,5340.97)
SDQS0N:  | length 677.9
  内层2 w5: v3(4933.24,5136.1) 4926.21,5136.08 4921.22,5131.05 4921.22,5120.5 4928.28,5113.47 4944.5,5113.47 4996.22,5061.75 4996.22,5051.74 5023.74,5024.22 5224.55,5024.22 5232.8,5015.97 5372.71,5015.97 5379.21,5022.47 5488.39,5022.47 5508.24,5002.62 v3(5508.24,4996.51)
SDQS0P:  | length 658.6
  内层2 w5: v3(4906.72,5135.97) 4909.69,5133.02 4909.72,5115.72 4923.53,5101.97 4939.73,5101.97 4984.72,5056.98 4984.72,5046.97 5018.97,5012.72 5219.78,5012.72 5228.03,5004.47 5377.48,5004.47 5383.98,5010.97 5471.78,5010.97 v3(5486.24,4996.51)
SDQS1N:  | length 1118.3
  Inner5 w5: v3(4687.72,5135.97) 4687.72,5135.85 4691.7,5131.87 4691.7,5120.99 4700.22,5112.47 4700.22,5013.47 4745.97,4967.72 5639.98,4967.72 5651.72,4979.46 5651.72,4991.97 v3(5653.72,4993.97)
SDQS1P:  | length 1089.9
  Inner5 w5: v3(4712.72,5135.97) 4708.22,5135.97 4703.2,5130.95 4703.2,5125.76 4711.72,5117.24 4711.72,5018.24 4750.74,4979.22 5635.21,4979.22 5640.22,4984.23 5640.22,4988.97 5635.22,4993.97 v3(5631.72,4993.97)
SDQS2N:  | length 526.1
  内层2 w5: v3(4935.72,5497.97) 4935.72,5500.47 4940.72,5505.47 4946.95,5505.47 4955.45,5496.97 5035.71,5496.97 5050.21,5511.47 5068.23,5511.47 5078.97,5500.73 5078.97,5465.71 5199.22,5345.46 5199.22,5311.41 5242.66,5267.97 5279.21,5267.97 5286.22,5260.96 5286.22,5255.47 5280.72,5249.97 v3(5276.72,5249.97)
SDQS2P:  | length 536.8
  内层2 w5: v3(4935.72,5520.97) 4939.72,5516.97 4951.72,5516.97 4960.22,5508.47 5030.94,5508.47 5045.44,5522.97 5073,5522.97 5090.47,5505.5 5090.47,5470.48 5210.72,5350.23 5210.72,5316.18 5247.43,5279.47 5283.98,5279.47 5297.72,5265.73 5297.72,5251.97 v3(5299.72,5249.97)
SDQS3N:  | length 646.9
  Inner5 w5: v3(4713.72,5494.97) 4713.72,5499.97 4718.72,5504.97 4726.45,5504.97 4735.95,5495.47 4786.96,5495.47 4793.46,5488.97 4819.99,5488.97 4832.99,5501.97 4888.73,5501.97 4918.73,5471.97 4975.72,5471.97 4993.72,5453.97 5069.72,5453.97 5109.72,5413.97 5149.15,5413.97 5197.72,5365.4 5197.72,5331.98 5217.23,5312.47 5234.44,5312.47 5240.45,5306.46 v3(5240.97,5306.46)
SDQS3P:  | length 638.5
  Inner5 w5: v3(4715.72,5521.97) 4721.22,5516.47 4731.22,5516.47 4740.72,5506.97 4791.73,5506.97 4798.23,5500.47 4815.22,5500.47 4828.22,5513.47 4893.5,5513.47 4923.5,5483.47 4979.33,5483.47 4997.33,5465.47 5074.49,5465.47 5114.49,5425.47 5153.92,5425.47 5209.22,5370.17 5209.22,5336.75 5222,5323.97 5238.04,5323.97 v3(5240.72,5326.65)
SPI0-CLK: U18.6 | length 41.3
  Bottom Layer w4: U18.6@5585.03,5969 5610.8,5969 v1(5621.8,5958)
SPI0-CS: R73.1 U18.1 | length 142.3
  Bottom Layer w4: v1(5828.8,6074) U18.1@5897.57,6074 ; R73.1@5884.29,6135 5884.29,6087.28 U18.1@5897.57,6074 ; U18.1@5902.57,6069 U18.1@5897.57,6074
SPI0-HOLD: R75.1 U18.7 | length 93.8
  Bottom Layer w4: R75.1@5542.8,6019.49 5584.54,6019.49 5585.03,6019 5613.8,6019 v1(5629.8,6003)
SPI0-MISO: U18.2 | length 288.2
  Bottom Layer w4: v1(5830.8,5998) 5829.8,5998 5820.8,6007 5820.8,6050 5825.8,6055 5831.8,6055 5836.8,6050 5836.8,6011.76 5839.91,6008.66 5845.46,6008.66 5848.8,6012 5848.8,6050 5852.3,6053.5 5857.3,6053.5 5860.8,6050 5860.8,6010 5872.8,5998 5898.8,5998 5902.57,6001.77 U18.2@5902.57,6019
SPI0-MOSI: U18.5 | length 64.7
  Bottom Layer w4: U18.5@5585.03,5919 5615.8,5919 v1(5639.8,5943)
SPI0-WP: R74.1 U18.3 | length 297
  Bottom Layer w4: v1(5850.8,5970) 5838.8,5970 5823.8,5955 5823.8,5908 5828.8,5903 5836.57,5903 5840.8,5907.23 5840.8,5947 5845.8,5952 5853.8,5952 5862.8,5943 5908.8,5943 5914.8,5949 5914.8,5956.77 5902.57,5969 5949.31,5969 R74.1@5950.8,5970.49
SPI-LCD-BLK: R119.2 U16.4 | length 3591
  内层2 w5: v2(5162.8,5990) 5168.8,5990 5179.8,6001 5179.8,6033 5252.8,6106 5423.8,6106 5616.8,5913 5767.8,5913 5809.8,5955 5864.8,5955 5875.8,5966 6847.8,5966 6979.8,5834 v2(6979.8,5590)
  Bottom Layer w4: 5132.8,6343 5139.8,6343 5181.8,6301 5181.8,6210 5162.8,6191 v2(5162.8,5990) 5162.8,5875 5203.8,5834 5203.8,5803 5247.8,5759 5247.8,5696 5311.8,5632 5311.8,5609 5382.8,5538 v2(5386.8,5538)
  Bottom Layer w5: U16.4@6739.91,5431.15 6739.91,5548.11 6781.8,5590 v2(6979.8,5590)
SPI-LCD-CLK:  | length 3597.3
  内层2 w5: v2(5201.8,5959) 5210.8,5968 5210.8,6011 5276.8,6077 5403.8,6077 5596.8,5884 5791.8,5884 5832.8,5925 5884.8,5925 5896.8,5937 6828.8,5937 6943.8,5822 6943.8,5572 6964.8,5551 6964.8,5426 6920.8,5382 6920.8,5361 6945.8,5336 6945.8,5261 v2(6946.8,5260)
  Bottom Layer w4: 5332.8,6343 5332.8,6337 5285.8,6290 5285.8,6226 5247.8,6188 5224.8,6188 5201.8,6165 v2(5201.8,5959) 5201.8,5879 5227.8,5853 5227.8,5816 5273.8,5770 5273.8,5709 5336.8,5646 5336.8,5622 5389.8,5569 5395.8,5569 5418.8,5546 5454.8,5546 5457.8,5549 5468.8,5549 v1(5484.8,5533)
SPI-LCD-CS:  | length 3550.3
  内层2 w5: v2(5181.8,5974) 5184.8,5974 5194.8,5984 5194.8,6018 5266.8,6090 5413.8,6090 5605.8,5898 5777.8,5898 5819.8,5940 5874.8,5940 5885.8,5951 6839.8,5951 6961.8,5829 6961.8,5576 6979.8,5558 6979.8,5414 6961.8,5396 6961.8,5250 6950.8,5239 6939.8,5239 6926.8,5252 6909.8,5252 v2(6900.8,5243)
  Bottom Layer w4: 5232.8,6243 5232.8,6230.05 5181.8,6179.05 v2(5181.8,5974) 5181.8,5877 5215.8,5843 5215.8,5809 5260.8,5764 5260.8,5704 5324.8,5640 5324.8,5616 5387.8,5553 5394.8,5553 5414.8,5533 v1(5464.8,5533)
SPI-LCD-DC:  | length 3517.6
  内层2 w5: v2(5239.8,5928) 5239.8,5996 5293.8,6050 5391.8,6050 5585.8,5856 5814.8,5856 5852.8,5894 5898.8,5894 5912.8,5908 6810.8,5908 6905.8,5813 6905.8,5555 6934.8,5526 6934.8,5449 6887.8,5402 6887.8,5329 6926.8,5290 v2(6926.8,5278)
  Bottom Layer w3: 5428.8,5573 5447.8,5573 5458.8,5584 5472.8,5584 v1(5485.8,5571)
  Bottom Layer w4: 5428.8,5573 5361.8,5640 5361.8,5662 5301.8,5722 5301.8,5779 5252.8,5828 5252.8,5870 5239.8,5883 v2(5239.8,5928) 5239.8,6140 5250.8,6151 5269.8,6151 5310.8,6192 5362.8,6192 5385.8,6215 5385.8,6297 5403.72,6314.91 5404.72,6314.91 5432.8,6343
SPI-LCD-MOSI:  | length 3356.7
  内层2 w5: v2(5219.8,5943) 5224.8,5948 5224.8,6002 5285.8,6063 5397.8,6063 5591.8,5869 5803.8,5869 5845.8,5911 5892.8,5911 5904.8,5923 6819.8,5923 6923.8,5819 6923.8,5565 6950.8,5538 6950.8,5439 6904.8,5393 6904.8,5338 v2(6928.8,5314)
  Bottom Layer w4: 5332.8,6243 5331.8,6243 5259.8,6171 5236.8,6171 5219.8,6154 v2(5219.8,5943) 5219.8,5884 5239.8,5864 5239.8,5823 5287.8,5775 5287.8,5715 5348.8,5654 5348.8,5630 5394.8,5584 5400.8,5584 5427.8,5557 5451.8,5557 v1(5465.8,5571)
SPI-LCD-RST:  | length 3572.6
  内层2 w5: v2(5146.8,6009) 5146.8,6021 5246.8,6121 5431.8,6121 5626.8,5926 5753.8,5926 5801.8,5974 5831.8,5974 5843.8,5986 5867.8,5986 5871.8,5982 6853.8,5982 6997.8,5838 6997.8,5340 6977.8,5320 6977.8,5240 6957.8,5220 6930.8,5220 v2(6924.8,5226)
  Bottom Layer w4: 5132.8,6243 5146.8,6229 v2(5146.8,6009) 5146.8,5871 5193.8,5824 5193.8,5797 5235.8,5755 5235.8,5693 5299.8,5629 5299.8,5604 v1(5386.8,5517)
SRST:  | length 1056.2
  内层2 w4.5: v3(4685.2,5438.97) 4710.2,5463.97 4768.72,5463.97 4792.72,5439.97 4835.72,5439.97 4852.72,5456.97 4890.72,5456.97 4896.72,5450.97 4914.72,5450.97 4924.72,5460.97 4972.72,5460.97 4984.72,5448.97 4984.72,5439.97 5062.72,5361.97 5084.38,5361.97 5116.72,5329.63 5116.72,5310.97 5105.72,5299.97 5105.72,5283.99 5114.74,5274.97 5131.72,5274.97 5180.72,5225.97 5375.72,5225.97 5396.72,5204.97 5535.2,5204.97 v3(5548.41,5218.18)
STWI1-SCK:  | length 717.6
  Bottom Layer w4: 4932.3,6342.5 4972.07,6302.74 ; 4972.07,6303.74 4972.07,6302.74 ; v2(5166.8,5723) 5162.8,5727 5162.8,5809 5114.8,5857 5114.8,6007 5021.8,6100 5021.8,6184 4984.8,6221 4984.8,6290 4972.07,6302.74
STWI1-SDA:  | length 569
  Bottom Layer w4: 5032.8,6243 5034.8,6241 5034.8,6104 5128.8,6010 5128.8,5864 5179.8,5813 5179.8,5742 v2(5184.8,5737)
UART1-CTS:  | length 1922.3
  Inner5 w4: v1(4095.8,5870) 4181.8,5956 5103.8,5956 5258.8,5801 5496.8,5801 5549.8,5748 5611.8,5748 5724.8,5635 5770.8,5635 5784.8,5621 5784.8,5596.03 v1(5760.78,5572.01)
UART1-RTS:  | length 1923.7
  Inner5 w4: v1(4071.8,5871) 4169.8,5969 5106.8,5969 5262.8,5813 5499.8,5813 5553.8,5759 5617.8,5759 5730.8,5646 5776.8,5646 5800.15,5622.66 v1(5800.15,5611.38)
UART1-RX:  | length 1998.3
  Inner5 w4: v1(4049.8,5873) 4158.8,5982 5110.8,5982 5264.8,5828 5500.8,5828 5558.8,5770 5622.8,5770 5735.8,5657 5785.8,5657 5813.8,5629 5813.8,5605.33 v1(5800.16,5591.69)
UART1-TX:  | length 2071.3
  Inner5 w4: v1(4026.8,5874) 4147.8,5995 5114.8,5995 5270.8,5839 5507.8,5839 5566.8,5780 5628.8,5780 5739.8,5669 5790.8,5669 5825.8,5634 5825.8,5597.66 v1(5800.16,5572.01)
  other v1: 4026.8,5874
USB0-DM:  | length 1020.5
  VCC w5: v1(6283.8,5210) 6283.8,5223.37 6289.3,5228.87 6289.3,5304.23 6524.8,5539.73 6524.8,5800 6689.8,5965 6689.8,6013 v1(6682.8,6020)
  Bottom Layer w5: v1(6681.8,6117) 6719.8,6117 v1(6720.8,6118)
USB0-DP:  | length 978.1
  VCC w5: v1(6303.8,5213) 6303.8,5223.37 6298.3,5228.87 6298.3,5298.5 6535.8,5536 6535.8,5797 6698.8,5960 6698.8,6013 v1(6705.8,6020)
USB0-DRVVBUS:  | length 3327.3
  内层2 w4: v2(5036.8,5729) 5067.8,5698 5078.8,5698 5093.8,5683 5117.8,5683 5153.8,5647 5262.8,5647 5325.8,5584 5325.8,5446 5341.8,5430 5373.8,5430 5443.8,5360 5463.8,5360 5476.8,5347 5525.8,5347 v2(5562.8,5310)
  内层4 w6: v2(4978.8,6015) 5076.8,6113 5851.8,6113 5959.8,6005 6777.8,6005 6910.8,6138 6929.8,6138 6941.8,6126 6941.8,6078 v2(6995.8,6024)
  Bottom Layer w4: v2(4978.8,6015) 5014.8,5979 5014.8,5787 5041.8,5760 5041.8,5734 v2(5036.8,5729)
USB0-VBUSDET:  | length 3107
  内层2 w4: v2(5059.8,5732) 5078.8,5713 5084.8,5713 5099.8,5698 5121.8,5698 5161.8,5658 5270.8,5658 5336.8,5592 5336.8,5451 5347.8,5440 5377.8,5440 5446.8,5371 5469.8,5371 5481.8,5359 5536.8,5359 v2(5562.8,5333)
  内层4 w6: v2(5001.8,6015) 5081.8,6095 5841.8,6095 5947.8,5989 6785.8,5989 v1(6918.8,6122)
  Bottom Layer w4: v2(5001.8,6015) 5026.8,5990 5026.8,5793 5052.8,5767 5052.8,5739 v2(5059.8,5732)
USB1-DM:  | length 2966.5
  Bottom Layer w5: v1(4602.8,4135) 4597.8,4130 4597.8,4055 4575.8,4033 4428.58,4033 4373.3,4088.27 4373.3,4240.23 4701.08,4568 5054.08,4568 5173.08,4687 5940.8,4687 6129.8,4876 6129.8,5138 6073.8,5194 6044.24,5194 6014.45,5223.79 5990.87,5223.79 v1(5977,5237.67)
USB1-DP:  | length 2983.5
  Bottom Layer w5: v1(4582.8,4135) 4588.8,4129 4588.8,4124.24 4583.8,4119.24 4573.4,4119.24 4568.4,4114.24 4568.4,4109.24 4573.4,4104.24 4583.8,4104.24 4588.8,4099.24 4588.8,4094.24 4583.8,4089.24 4573.4,4089.24 4568.4,4084.24 4568.4,4079.24 4573.4,4074.24 4583.8,4074.24 4588.8,4069.24 4588.8,4060 4571.8,4043 4431.3,4043 4382.3,4092 4382.3,4236.5 4704.8,4559 5057.8,4559 5177.8,4679 5945.53,4679 6137.8,4871.27 6137.8,5141.31 6076.12,5203 6047.97,5203 6018.18,5232.79 6011.95,5232.79 6007.07,5237.67 v1(5996.7,5237.67)
USB2-DM:  | length 3315.2
  Bottom Layer w5: v1(4282.8,4019) 4282.8,4008.63 4277.31,4003.13 4277.31,4000.63 4299.94,3978 4326.54,3978 4350.82,3953.72 4350.82,3912.98 4383.44,3880.36 4383.44,3857.11 4397.55,3843 4448.8,3843 4460.8,3855 4460.8,3863 4452.97,3870.83 4425.43,3870.83 ; v1(4411.8,4170) 4418.8,4177 4418.8,4222.73 4428.28,4232.21 4428.28,4239.28 4435.35,4246.35 4442.43,4246.35 4449.5,4253.42 4449.5,4260.49 4456.57,4267.56 4463.64,4267.56 4470.71,4274.63 4470.71,4281.71 4477.78,4288.78 4484.85,4288.78 4491.92,4295.85 4491.92,4302.92 4498.99,4309.99 4506.07,4309.99 4513.14,4317.06 4513.14,4324.13 4520.21,4331.2 4527.28,4331.2 4534.35,4338.27 4534.35,4345.35 4541.42,4352.42 4548.49,4352.42 4555.56,4359.49 4555.56,4366.56 4562.63,4373.63 4569.7,4373.63 4576.78,4380.7 4576.78,4387.77 4583.85,4394.84 4590.92,4394.84 4597.99,4401.91 4597.99,4408.98 4605.06,4416.06 4612.13,4416.06 4619.2,4423.13 4619.2,4430.2 4626.27,4437.27 4633.34,4437.27 4640.42,4444.34 4640.42,4451.41 4647.49,4458.48 4654.56,4458.48 4661.63,4465.55 4661.63,4472.62 4668.7,4479.7 4675.77,4479.7 4720.08,4524 5069.08,4524 5202.08,4657 6283.8,4657 6323.8,4697 6323.8,4747.27 6235.8,4835.27 6235.8,4948.27 6155.8,5028.27 6155.8,5143 6082.8,5216 6061.61,5216 6014.45,5263.17 5990.87,5263.17 v1(5977,5277.04)
USB2-DP:  | length 3288.9
  Bottom Layer w5: v1(4262.8,4019) 4262.8,4008.63 4268.3,4003.13 4268.3,3996.9 4296.21,3968.98 4322.8,3968.98 4341.8,3949.98 4341.8,3909.25 4374.43,3876.62 4374.43,3853.38 4393.82,3833.98 4452.54,3833.98 4469.82,3851.27 4469.82,3863.02 4479.8,3873 4502,3873 4504.17,3870.83 ; v1(4437.8,4170) 4427.8,4180 4427.8,4219 4723.8,4515 5072.8,4515 5206.8,4649 6288.53,4649 6332.8,4693.27 6332.8,4751 6244.8,4839 6244.8,4952 6164.8,5032 6164.8,5146.73 6086.53,5225 6065.34,5225 6018.18,5272.17 6011.95,5272.17 6007.07,5277.04 v1(5996.7,5277.04)
USB2-RXN:  | length 2888.2
  Bottom Layer w5: v1(4548.8,4135) 4541.8,4142 4541.8,4200 4776.8,4435 5111.53,4435 5258.53,4582 6331.53,4582 6451.8,4702.27 6451.8,4904.73 6334.53,5022 6273.8,5022 6223.8,5072 6223.8,5178 6166.74,5235.06 6166.74,5237.56 6168.8,5239.63 v1(6168.8,5250)
USB2-RXP:  | length 2930.1
  Bottom Layer w5: v1(4527.8,4135) 4533.8,4141 4533.8,4155.37 4528.8,4160.37 4515.8,4160.37 4510.8,4165.37 4510.8,4170.37 4515.8,4175.37 4528.8,4175.37 4533.8,4180.37 4533.8,4204.73 4773.08,4444 5107.8,4444 5254.8,4591 6327.8,4591 6442.8,4706 6442.8,4901 6330.8,5013 6270.08,5013 6214.8,5068.27 6214.8,5175.69 6149.8,5240.69 v1(6149.8,5256)
USB2-TXN:  | length 2883.2
  Bottom Layer w5: v1(4488.8,4180) 4482.8,4186 4482.8,4202.27 4750.9,4470.36 5086.17,4470.36 5228.8,4613 6303.53,4613 6414.8,4724.27 6414.8,4894.73 6323.53,4986 6257.8,4986 6190.8,5053 6190.8,5158 6123.3,5225.5 6123.3,5256.13 6128.8,5261.63 v1(6128.8,5273)
USB2-TXP:  | length 2933.4
  Bottom Layer w5: v1(4468.8,4180) 4473.8,4185 4473.8,4206 4482.76,4214.96 4482.76,4225.96 4487.87,4231.07 4498.87,4231.07 4503.98,4236.17 4503.98,4247.17 4509.08,4252.28 4520.08,4252.28 4525.19,4257.39 4525.19,4268.39 4530.3,4273.49 4541.3,4273.49 4546.4,4278.6 4546.4,4289.6 4551.51,4294.71 4562.51,4294.71 4567.62,4299.81 4567.62,4310.81 4572.72,4315.92 4583.72,4315.92 4588.83,4321.03 4588.83,4332.03 4593.94,4337.13 4604.94,4337.13 4610.04,4342.24 4610.04,4353.24 4615.15,4358.35 4626.15,4358.35 4631.26,4363.45 4631.26,4374.45 4636.36,4379.56 4647.36,4379.56 4747.17,4479.36 5082.44,4479.36 5226.08,4623 6300.8,4623 6405.8,4728 6405.8,4891 6319.8,4977 6254.08,4977 6181.8,5049.27 6181.8,5154 6114.3,5221.5 6114.3,5256.13 6108.8,5261.63 v1(6108.8,5272)
VBUS: C246.2 C247.2 C294.2 FPC1.1 FPC1.2 U11.3 | length 12006.2
  内层4 w20: v2(4824.26,4119.46) v2(4837.15,4132.35) 4975.8,4271 5295.8,4271 5342.8,4318 5580.8,4318 5660.8,4398 5716.8,4398 5760.8,4442 6000.8,4442 6034.8,4408 6200.8,4408 6269.8,4339 6418.8,4339 6505.8,4426 7095.8,4426 7164.8,4357 v2(7164.8,4336)
  Inner5 w20: v2(3394.8,4100.96) 3471.8,4177.96 3471.8,4212 ; 3566.8,6213 3566.8,6277 3632.8,6343 3732.8,6343 ; v1(7129.8,6093) v1(7111.8,6093) 7093.8,6075 7093.8,5937 7112.8,5918 7112.8,5661 7063.8,5612 7063.8,5474 7089.8,5448 7089.8,5368 7164.8,5293 v2(7164.8,4336)
  Inner5 w50: 3419.8,4968 3419.8,5492 3406.61,5505.2 3406.61,5613.8 3435.8,5643 3435.8,6031.56 ; 3427.78,4964.14 3447.8,4945 ; 3434.8,6038 3435.8,6037 3435.8,6031.56 ; 3566.8,6213 3566.8,6162.56 3435.8,6031.56 ; v2(3612.8,4934) 3612.8,5005 3653.8,5046 ; 3698.8,5112 3698.8,5128 ; 3724.8,5159 3724.8,5164 v4(3712.8,5176) ; 4183.8,4047 4215.8,4079 4730.8,4079 4757.8,4052 ; 4191.8,4041 4053.8,4041 4009.8,3997 3577.8,3997 3484.8,4090 3484.8,4217 3447.8,4254 3447.8,4945 ; 3447.8,4945 3548.8,5046 3553.66,5046 ; 3553.66,5046 3683.66,5176 v4(3712.8,5176) ; 3553.66,5046 3616.8,5046 ; 3616.8,5046 3698.8,5128 ; 3616.8,5046 3653.8,5046 ; 3653.8,5046 3746.8,5139 3745.8,5140 v4(3745.8,5141) v4(3745.8,5175) ; 3698.8,5128 v4(3745.8,5175) ; 3698.8,5128 3698.8,5162 v4(3712.8,5176) ; v4(3712.8,5176) 3744.8,5176 v4(3745.8,5175)
  Bottom Layer w8: v1(4879.8,4336) v1(4879.8,4384)
  Bottom Layer w10: FPC1.2@3538.78,4927.6 3606.4,4927.6 v2(3612.8,4934) ; FPC1.1@3538.78,4947.28 3599.52,4947.28 v2(3612.8,4934) ; C247.2@3612.8,4955 v2(3612.8,4934)
  Bottom Layer w20: 4327.01,3744.85 4345.8,3763.64 4345.8,3852.04 4327.01,3870.83 ; v2(4748.75,4043.95) 4756.95,4052.15 v2(4764.63,4059.82) v2(4824.26,4119.46) ; v2(4837.15,4132.35) 4879.8,4175 v1(4879.8,4336) ; C246.2@7158.8,4455.28 7162.8,4451.28 U11.3@7162.8,4392.61 7164.8,4390.61 v2(7164.8,4336)
  Bottom Layer w30: v2(3999.8,4879.95) v2(3999.8,4900) 3999.8,4929 3975.8,4953 3945.8,4953 3806.39,5092.41 ; 3801.8,5099 3806.39,5094.41 3806.39,5092.41 ; 3801.8,5099 3801.8,5097 3806.39,5092.41 ; 3801.8,5099 3801.8,5133 3759.8,5175 v4(3745.8,5175) v4(3745.8,5141) 3787.8,5099 3801.8,5099
  Bottom Layer w50: 4327.01,3744.85 4327.01,3668.79 4460.8,3535 4762.8,3535 4823.8,3596 4823.8,3985.3 4756.95,4052.15 C294.2@4752.8,4056.3
  other v1: 3484.01,5375.6 3484.01,5398.17 3484.01,5419.14 3484.01,5440 3523.8,5443
  other v2: 4777.8,4037 4734.8,4071 3503.8,5441
  other v4: 3710.8,5144.76 3679.8,5176.67
VCC-3V3-BLK: C277.2 R126.2 U16.1 | length 82.2
  Bottom Layer w10: U16.1@6814.71,5340.31 6814.81,5340.21 R126.2@6814.81,5286 6816.81,5284 C277.2@6841.8,5284
VCC-LDO-RTC: C92.2 | length 2604.5
  内层2 w6: v1(3568.8,5314) 3568.8,5433 v2(3573.8,5438)
  Inner5 w15: v2(3537.3,5656.51) 3579.8,5614 3810.8,5614 3815.8,5609 3856.8,5609 3881.8,5584 v2(3893.8,5584)
  Bottom Layer w6: v2(3537.3,5656.51) 3550.8,5643 3592.8,5643 3598.8,5637 3598.8,5463 v2(3573.8,5438)
  Bottom Layer w8: v2(3893.8,5584) 3954.8,5645 5183.8,5645 5351.42,5477.38 5580.42,5477.38 v2(5602.8,5455)
VCM-ADC: C112.2 | length 24.2
  Bottom Layer w8: C112.2@5671.8,5533 5672.8,5532 5672.8,5525 5681.72,5516.08 v2(5681.72,5512.95)
VDD-CPUBFB:  | length 2756.6
  内层2 w10: v1(4005.8,5219) 4053.8,5219 4388.8,5554 4388.8,5668 4577.8,5857 5391.8,5857 5511.8,5737 5511.8,5723 5548.8,5686 5572.8,5686 5676.8,5582 5718.8,5582 5734.8,5566 5734.8,5532 5758.8,5508 5760.8,5508 5760.8,5481 5742.8,5463 5742.8,5443 5751.8,5434 5774.8,5434 5816.8,5392 5816.8,5325.12 5839.8,5302.12 5839.8,5289.88 5806.97,5257.04 v2(5780.16,5257.04)
  Bottom Layer w10: v1(4005.8,5219) 4022.8,5219 4040.8,5201 4040.8,5172 4016.8,5148 v1(4016.8,5108)
VDD-CPULFB:  | length 2415
  Inner5 w10: v1(3742.8,5361) 3730.8,5349 3730.8,5265 3769.8,5226 3857.8,5226 4027.8,5396 4329.8,5396 4603.8,5670 5142.8,5670 5338.8,5474 5361.8,5474 5372.8,5463 5372.8,5440 5395.8,5417 5432.8,5417 5453.8,5396 5589.8,5396 5602.8,5383 5621.8,5383 5638.8,5366 5638.8,5327 5649.8,5316 v2(5661.8,5316)
VDD-DNRFB:  | length 2001.6
  VCC w10: v2(3925.8,5268) 3943.8,5286 4203.8,5286 4576.8,5659 5126.8,5659 5387.8,5398 5606.14,5398 v2(5642.35,5434.21)
VDD-SYSFB:  | length 2543.2
  内层4 w10: v1(3638.8,5592) 3638.8,5665 3679.8,5706 3679.8,5755 3748.8,5824 3870.8,5824 3894.8,5800 3985.8,5800 4111.8,5674 5111.8,5674 5390.8,5395 5634.8,5395 5694.8,5335 5784.65,5335 5799.8,5350.15 v2(5799.8,5356)
VRA1: C109.2 | length 20.6
  Bottom Layer w6: v1(5562.93,5591.69) 5580.11,5591.69 C109.2@5582.55,5589.25
VRA2: C110.2 | length 19.7
  Bottom Layer w6: v1(5562.93,5611.38) 5582.42,5611.38 C110.2@5582.55,5611.25
VREFP-ADC: C113.2 R24.1 | length 50.7
  Bottom Layer w4: R24.1@5659.29,5491 5659.29,5510.2 v1(5662.05,5512.95)
  Bottom Layer w8: C113.2@5643.8,5533 5662.05,5514.76 v1(5662.05,5512.95)
VRP: C111.2 | length 38
  Bottom Layer w7: v1(5622.68,5552.32) 5625.8,5555.45 C111.2@5625.8,5589
WL-REG-ON:  | length 38
  Bottom Layer w4: v1(4009.8,5577) v1(4047.8,5577)
pads on no net: FPC1.34 FPC1.45 FPC1.46 FPC1.47 FPC1.48 FPC1.49 FPC2.1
